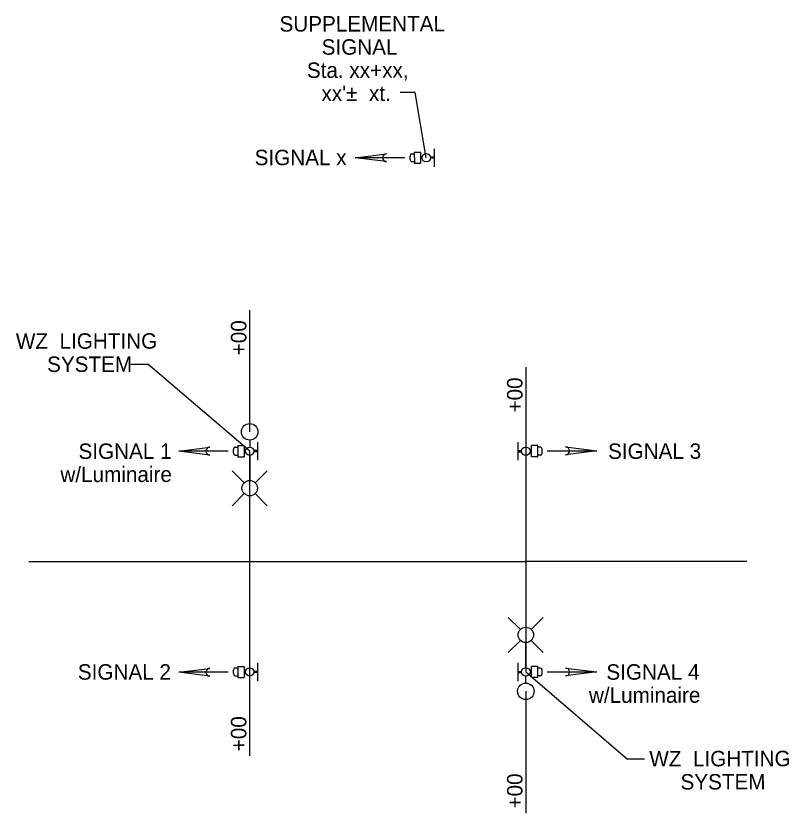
# Model space of a CAD drawing. Extents: x -1395 to 1843, y -1176 to 1887.
# Drawn here: x -711.1 to -571.1, y 365.6 to 510 of the extents above; entities that cross this region are included whole.
import ezdxf

# ---------------------------------------------------------------- set-up
doc = ezdxf.new("R2010")
doc.units = 0
for name, color, linetype in [('SH_Named_Boundary', 7, 'Continuous'), ('SH_Text', 7, 'Continuous'), ('XS_P_Pavt_Surface', 7, 'Continuous')]:
    doc.layers.add(name, color=color, linetype=linetype)

msp = doc.modelspace()

# ---------------------------------------------------------------- linework, layer by layer
at = {"layer": 'SH_Named_Boundary'}
for p, q in [((-690.25, 446.96), (-687.19, 446.96)), ((-668.76, 391.17), (-668.76, 431.17)), ((-618.76, 431.17), (-618.76, 391.17)), ((-708.76, 411.17), (-668.76, 411.17)), ((-668.76, 411.17), (-618.76, 411.17)), ((-578.76, 411.17), (-618.76, 411.17)), ((-597.27, 375.39), (-600.34, 375.39))]:
    msp.add_line(p, q, dxfattribs=at)
at = {"layer": 'SH_Text'}
for p, q in [((-638.95, 485.34), (-637.8, 485.34)), ((-638.95, 485.34), (-638.94, 483.33)), ((-637.8, 485.34), (-637.8, 483.33)), ((-635.38, 485.98), (-635.38, 482.69)), ((-649.63, 484.33), (-644, 485.03)), ((-640.68, 484.33), (-649.63, 484.33)), ((-644, 483.63), (-649.63, 484.33)), ((-639.44, 485.07), (-638.95, 485.07)), ((-637.54, 484.44), (-637.8, 484.44)), ((-637.54, 484.24), (-637.8, 484.24)), ((-635.38, 484.44), (-636.04, 484.44)), ((-635.38, 484.24), (-636.04, 484.24)), ((-639.44, 483.63), (-638.95, 483.63)), ((-638.96, 483.33), (-637.8, 483.33)), ((-681.6, 431.17), (-675.98, 431.88)), ((-671.41, 431.91), (-670.93, 431.91)), ((-670.92, 432.18), (-669.77, 432.18)), ((-670.92, 432.18), (-670.92, 430.17)), ((-669.77, 432.18), (-669.77, 430.17)), ((-668.76, 433.19), (-668.76, 431.93)), ((-667.35, 432.82), (-667.35, 429.53)), ((-620.17, 429.53), (-620.17, 432.82)), ((-616.59, 432.19), (-617.75, 432.18)), ((-617.75, 430.17), (-617.75, 432.18)), ((-616.6, 430.17), (-616.6, 432.19)), ((-616.11, 431.88), (-616.6, 431.88)), ((-611.55, 431.93), (-605.92, 431.23)), ((-672.66, 431.17), (-681.6, 431.17)), ((-675.98, 430.47), (-681.6, 431.17)), ((-671.41, 430.47), (-670.93, 430.47)), ((-669.51, 431.27), (-669.77, 431.27)), ((-669.51, 431.07), (-669.77, 431.07)), ((-668.76, 430.42), (-668.76, 425.87)), ((-667.35, 431.27), (-668.01, 431.27)), ((-667.35, 431.07), (-668.01, 431.07)), ((-620.17, 431.27), (-619.51, 431.27)), ((-620.17, 431.07), (-619.51, 431.07)), ((-618.01, 431.28), (-617.75, 431.28)), ((-618.01, 431.08), (-617.75, 431.08)), ((-616.11, 430.44), (-616.6, 430.44)), ((-614.87, 431.23), (-605.92, 431.23)), ((-605.92, 431.23), (-611.55, 430.53)), ((-670.93, 430.17), (-669.77, 430.17)), ((-616.6, 430.17), (-617.75, 430.17)), ((-669.75, 425.46), (-671.93, 427.64)), ((-667.77, 425.46), (-665.59, 427.64)), ((-669.75, 423.48), (-671.93, 421.29)), ((-667.77, 423.48), (-665.59, 421.29)), ((-619.75, 398.87), (-621.93, 401.05)), ((-617.77, 398.87), (-615.59, 401.05)), ((-619.75, 396.89), (-621.93, 394.71)), ((-618.76, 391.93), (-618.76, 396.48)), ((-617.77, 396.89), (-615.59, 394.71)), ((-681.6, 391.12), (-675.97, 391.82)), ((-671.41, 391.91), (-670.93, 391.91)), ((-670.92, 392.18), (-669.78, 392.18)), ((-670.92, 392.18), (-670.92, 390.16)), ((-669.78, 392.18), (-669.77, 390.16)), ((-667.35, 392.82), (-667.35, 389.53)), ((-620.17, 389.53), (-620.17, 392.82)), ((-617.75, 390.17), (-617.75, 392.18)), ((-616.59, 392.18), (-617.75, 392.18)), ((-616.6, 390.17), (-616.6, 392.18)), ((-616.11, 391.88), (-616.6, 391.88)), ((-611.55, 391.88), (-605.92, 391.17)), ((-672.65, 391.12), (-681.6, 391.12)), ((-675.97, 390.42), (-681.6, 391.12)), ((-671.41, 390.47), (-670.93, 390.47)), ((-670.93, 390.16), (-669.77, 390.16)), ((-669.51, 391.27), (-669.77, 391.27)), ((-669.51, 391.07), (-669.77, 391.07)), ((-667.35, 391.28), (-668.01, 391.28)), ((-667.35, 391.08), (-668.01, 391.08)), ((-620.17, 391.27), (-619.51, 391.27)), ((-620.17, 391.07), (-619.51, 391.07)), ((-618.76, 389.16), (-618.76, 390.42)), ((-618.01, 391.27), (-617.75, 391.27)), ((-618.01, 391.07), (-617.75, 391.07)), ((-616.6, 390.17), (-617.75, 390.17)), ((-616.11, 390.44), (-616.6, 390.44)), ((-614.87, 391.17), (-605.92, 391.17)), ((-605.92, 391.17), (-611.55, 390.47))]:
    msp.add_line(p, q, dxfattribs=at)
for centre, radius in [((-636.79, 484.34), 0.757), ((-668.76, 434.68), 1.5), ((-668.76, 431.17), 0.757), ((-618.76, 431.17), 0.757), ((-668.76, 424.47), 1.4), ((-618.76, 397.88), 1.4), ((-668.76, 391.17), 0.757), ((-618.76, 391.17), 0.757), ((-618.76, 387.66), 1.5)]:
    msp.add_circle(centre, radius, dxfattribs=at)
for centre, radius, start, end in [((-644, 484.33), 0.703, 90, 270), ((-675.98, 431.17), 0.703, 90, 270), ((-611.55, 431.23), 0.702, 270, 90), ((-675.97, 391.12), 0.702, 90, 270), ((-611.55, 391.17), 0.703, 270, 90)]:
    msp.add_arc(centre, radius, start, end, dxfattribs=at)
for centre, major_axis in [((-639.44, 484.35), (-0.001, 0.721)), ((-671.41, 431.19), (0, 0.721)), ((-616.11, 431.16), (0.001, -0.721)), ((-671.41, 391.19), (-0.001, 0.721)), ((-616.11, 391.16), (0, -0.721))]:
    msp.add_ellipse(centre, major_axis=major_axis, ratio=0.45371, start_param=0, end_param=3.141593, dxfattribs=at)
at = {"layer": 'XS_P_Pavt_Surface'}
for p, q in [((-638.82, 496.19), (-641.54, 496.19)), ((-636.79, 484.34), (-638.82, 496.19)), ((-668.75, 434.68), (-668.75, 456.74)), ((-668.76, 431.17), (-687.19, 446.96)), ((-618.76, 446.37), (-618.76, 431.17)), ((-668.76, 375.98), (-668.76, 391.17)), ((-618.76, 391.17), (-600.34, 375.39)), ((-618.77, 387.66), (-618.77, 365.6))]:
    msp.add_line(p, q, dxfattribs=at)

# ---------------------------------------------------------------- texts
at = {"layer": 'SH_Named_Boundary'}
for s, rotation, p in [('SUPPLEMENTAL', 0.0871, (-663.36, 507.19)), ('SIGNAL', 0.0871, (-655.73, 503)), ('Sta. xx+xx,', 0.0871, (-658.4, 498.8)), ("xx'±  xt.", 0.0871, (-655.76, 494.6)), ('SIGNAL x', 0.0561, (-667.86, 482.98)), ('+00', 90.0561, (-669.35, 448.55)), ('WZ  LIGHTING', 0.0871, (-711.09, 449.71)), ('SYSTEM', 0.0871, (-705.44, 445.52)), ('+00', 90.0561, (-619.36, 438.18)), ('SIGNAL 1', 0.0871, (-699.75, 429.76)), ('SIGNAL 3', 0.0561, (-603.87, 429.77)), ('w/Luminaire', 0.0871, (-703.03, 425.56)), ('SIGNAL 2', 0.0561, (-699.87, 389.77)), ('SIGNAL 4', 0.0871, (-604.17, 389.76)), ('w/Luminaire', 0.0871, (-607.33, 385.56)), ('+00', 90.0561, (-669.36, 376.8)), ('WZ  LIGHTING', 0.0871, (-596.4, 374.05)), ('+00', 90.0561, (-619.36, 366.43)), ('SYSTEM', 0.0871, (-590.75, 369.86))]:
    msp.add_text(s, height=2.8, rotation=rotation, dxfattribs=at).set_placement(p)

doc.saveas('drawing.dxf')
